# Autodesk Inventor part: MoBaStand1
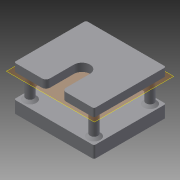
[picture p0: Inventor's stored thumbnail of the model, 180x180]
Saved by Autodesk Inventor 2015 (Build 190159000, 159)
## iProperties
Created: 2017-04
Part Number: MoBaStand1
Material: Generisch
Document SubType Name: Modeling
Designer: Andreas
Density: 1 g/cm^3
Appearance: Vorgabe
Author: Andreas
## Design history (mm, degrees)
sketch "base"
  geometry: L1 (0, 0)-(100, 0); L2 (100, 0)-(100, 90); L3 (100, 90)-(0, 90); L4 (0, 90)-(0, 0)
  constraints: 8 end point, 2 parallel, 1 horizontal, 1 perpendicular
  dimensions: "d0" = 100 distance of L3.end L2.end; "d1" = 90 distance of L2.end L1.end
extrude "ExtrusionBase" new body sketch "base" distance "d2" = 15; taper "d3" = 0 deg
sketch "middle"
  geometry: L1 (0, 0)-(100, 0) reference; L2 (100, 0)-(100, 90) reference; L3 (100, 90)-(0, 90) reference; L4 (0, 90)-(0, 0) reference; C1 r 5 at (10, 80); C2 r 5 at (90, 80); C3 r 5 at (90, 10); C4 r 5 at (10, 10); 1 further point
  constraints: 4 centre point
  dimensions: "d12" = 10 diameter of C1; "d13" = 10 diameter of C2; "d14" = 10 diameter of C3; "d15" = 10 diameter of C4
extrude "ExtrusionMiddle" join sketch "middle" distance "d16" = 30; taper "d17" = 0 deg
workplane "Arbeitsebene1"
sketch "top"
  geometry: L1 (0, 0)-(100, 0) reference; L2 (100, 0)-(100, 90) reference; L3 (100, 90)-(0, 90) reference; L4 (0, 90)-(0, 0) reference; L5 (0, 0)-(100, 0); L6 (100, 0)-(100, 90); L7 (100, 90)-(0, 90); L8 (0, 90)-(0, 0); C1 r 5 at (90, 10) reference; C2 r 5 at (10, 80) reference; C3 r 5 at (90, 80) reference; C4 r 5 at (10, 10) reference
  constraints: 8 end point, 2 parallel, 1 horizontal, 1 perpendicular
extrude "ExtrusionTop" join sketch "top" distance "d19" = 10; taper "d20" = 0 deg
sketch "cutout"
  geometry: L1 (0, 0)-(100, 0) reference; L2 (60, 0)-(40, 0); L3 (60, 35)-(60, 0); L4 (40, 0)-(40, 35); L5 (100, 0)-(100, 90) reference; A1 r 10 centre (50, 35) between (60, 35) and (40, 35); 3 further points
  constraints: 6 end point, 3 point on circle, 2 coincident, 2 point on line, 2 tangent, 1 centre point, 1 vertical
  dimensions: "d21" = 20 distance of L2.start L2.end; "d22" = 35 distance of L3.start L2.start; "d23" = 35 distance of L2.end L4.end; "d24" = 40 distance between parallel lines of L5 L3
extrude "ExtrusionCutout" cut sketch "cutout" distance "d25" = 10; taper "d26" = 0 deg
fillet "Rundung1" dims "d27" = 5
fillet "Rundung2" dims "d28" = 5
fillet "Rundung3" dims "d29" = 2
fillet "Rundung4" dims "d30" = 2
fillet "Rundung5" dims "d31" = 2
fillet "Rundung6" dims "d32" = 2
fillet "Rundung7" dims "d33" = 2
fillet "Rundung8" dims "d34" = 2
fillet "Rundung9" dims "d35" = 2
fillet "Rundung10" dims "d36" = 2
chamfer "Fase1" distance "d37" = 3; stored, may be unused: second distance "d38" = 2, angle "d39" = 45 deg
chamfer "Fase2" distance "d40" = 3; stored, may be unused: second distance "d41" = 2, angle "d42" = 45 deg
chamfer "Fase3" distance "d43" = 3; stored, may be unused: second distance "d44" = 2, angle "d45" = 45 deg
chamfer "Fase4" distance "d46" = 3; stored, may be unused: second distance "d47" = 2, angle "d48" = 45 deg
chamfer "Fase5" distance "d49" = 3; stored, may be unused: second distance "d50" = 2, angle "d51" = 45 deg
chamfer "Fase6" distance "d52" = 3; stored, may be unused: second distance "d53" = 2, angle "d54" = 45 deg
chamfer "Fase7" distance "d55" = 3; stored, may be unused: second distance "d56" = 2, angle "d57" = 45 deg
chamfer "Fase8" distance "d58" = 3; stored, may be unused: second distance "d59" = 2, angle "d60" = 45 deg
node "Volumenkörper1"
node "Projizierte Kontur1"
node "Projizierte Kontur3"
